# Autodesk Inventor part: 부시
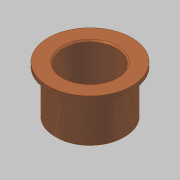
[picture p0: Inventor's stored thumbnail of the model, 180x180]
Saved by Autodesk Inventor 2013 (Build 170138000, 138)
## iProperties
Created: 2013-06
Part Number: 부시
Document SubType Name: Modeling
Designer: SeoGD™[esajin.kr]
Density: 1 g/cm^3
Material: 일반
Mass: 31.4212 g
Surface Area: 129.264 cm^2
Volume: 31.4212 cm^3
Author: SeoGD™[esajin.kr]
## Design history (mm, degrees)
sketch "스케치1"
  geometry: C1 r 31 at (0, 0) reference; C2 r 25 at (0, 0) reference; C3 r 30 at (0, 0) reference; 1 further point
  node "참조1"
  node "참조2"
  node "참조4"
extrude "돌출1" new body sketch "스케치1" distance "d0" = 3; taper "d1" = 0 deg
extrude "돌출2" join sketch "스케치1" distance "d2" = 35; taper "d3" = 0 deg
chamfer "모따기1" distance "d6" = 1; stored, may be unused: second distance "d7" = 2, angle "d8" = 45 deg
sketch "스케치3"
  geometry: C1 r 19 at (0, 0); 1 further point
  constraints: 1 centre point, 1 coincident
  dimensions: "d13" = 38 diameter of C1
extrude "돌출4" cut sketch "스케치3" stored distance "d14" = 10; taper "d15" = 0 deg
chamfer "모따기3" distance "d16" = 1; stored, may be unused: second distance "d17" = 2, angle "d18" = 45 deg
node "솔리드1"
